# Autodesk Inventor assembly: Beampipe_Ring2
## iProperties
Shininess: 64.0
Length Units: 11269
Angle Units: 11279
Time Units: 11290
Mass Units: 11283
Length Display Precision: 3
Angle Display Precision: 2
Compacted: True
Created: 2004-08
Part Number: Beampipe_Ring2
Document SubType Name: Assembly
Designer: John Blackburn
Manufacturer: Standard
Standards Organization: Custom
Density: 0.0
Volumn: 0.0
Area: 0.0
PropertySet Name: Model Information
Control State: 0
Master: False
Checked Out: False
Author: John Blackburn
